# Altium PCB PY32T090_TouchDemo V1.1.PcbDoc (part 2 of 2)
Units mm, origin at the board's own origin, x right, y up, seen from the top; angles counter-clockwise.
Board outline 86.5 x 140.97 mm, 2 copper layers (Top Layer, Bottom Layer); 152 components, 143 nets, 461 pads, 174 vias.
Unrouted connection lines stored in the file: 2.
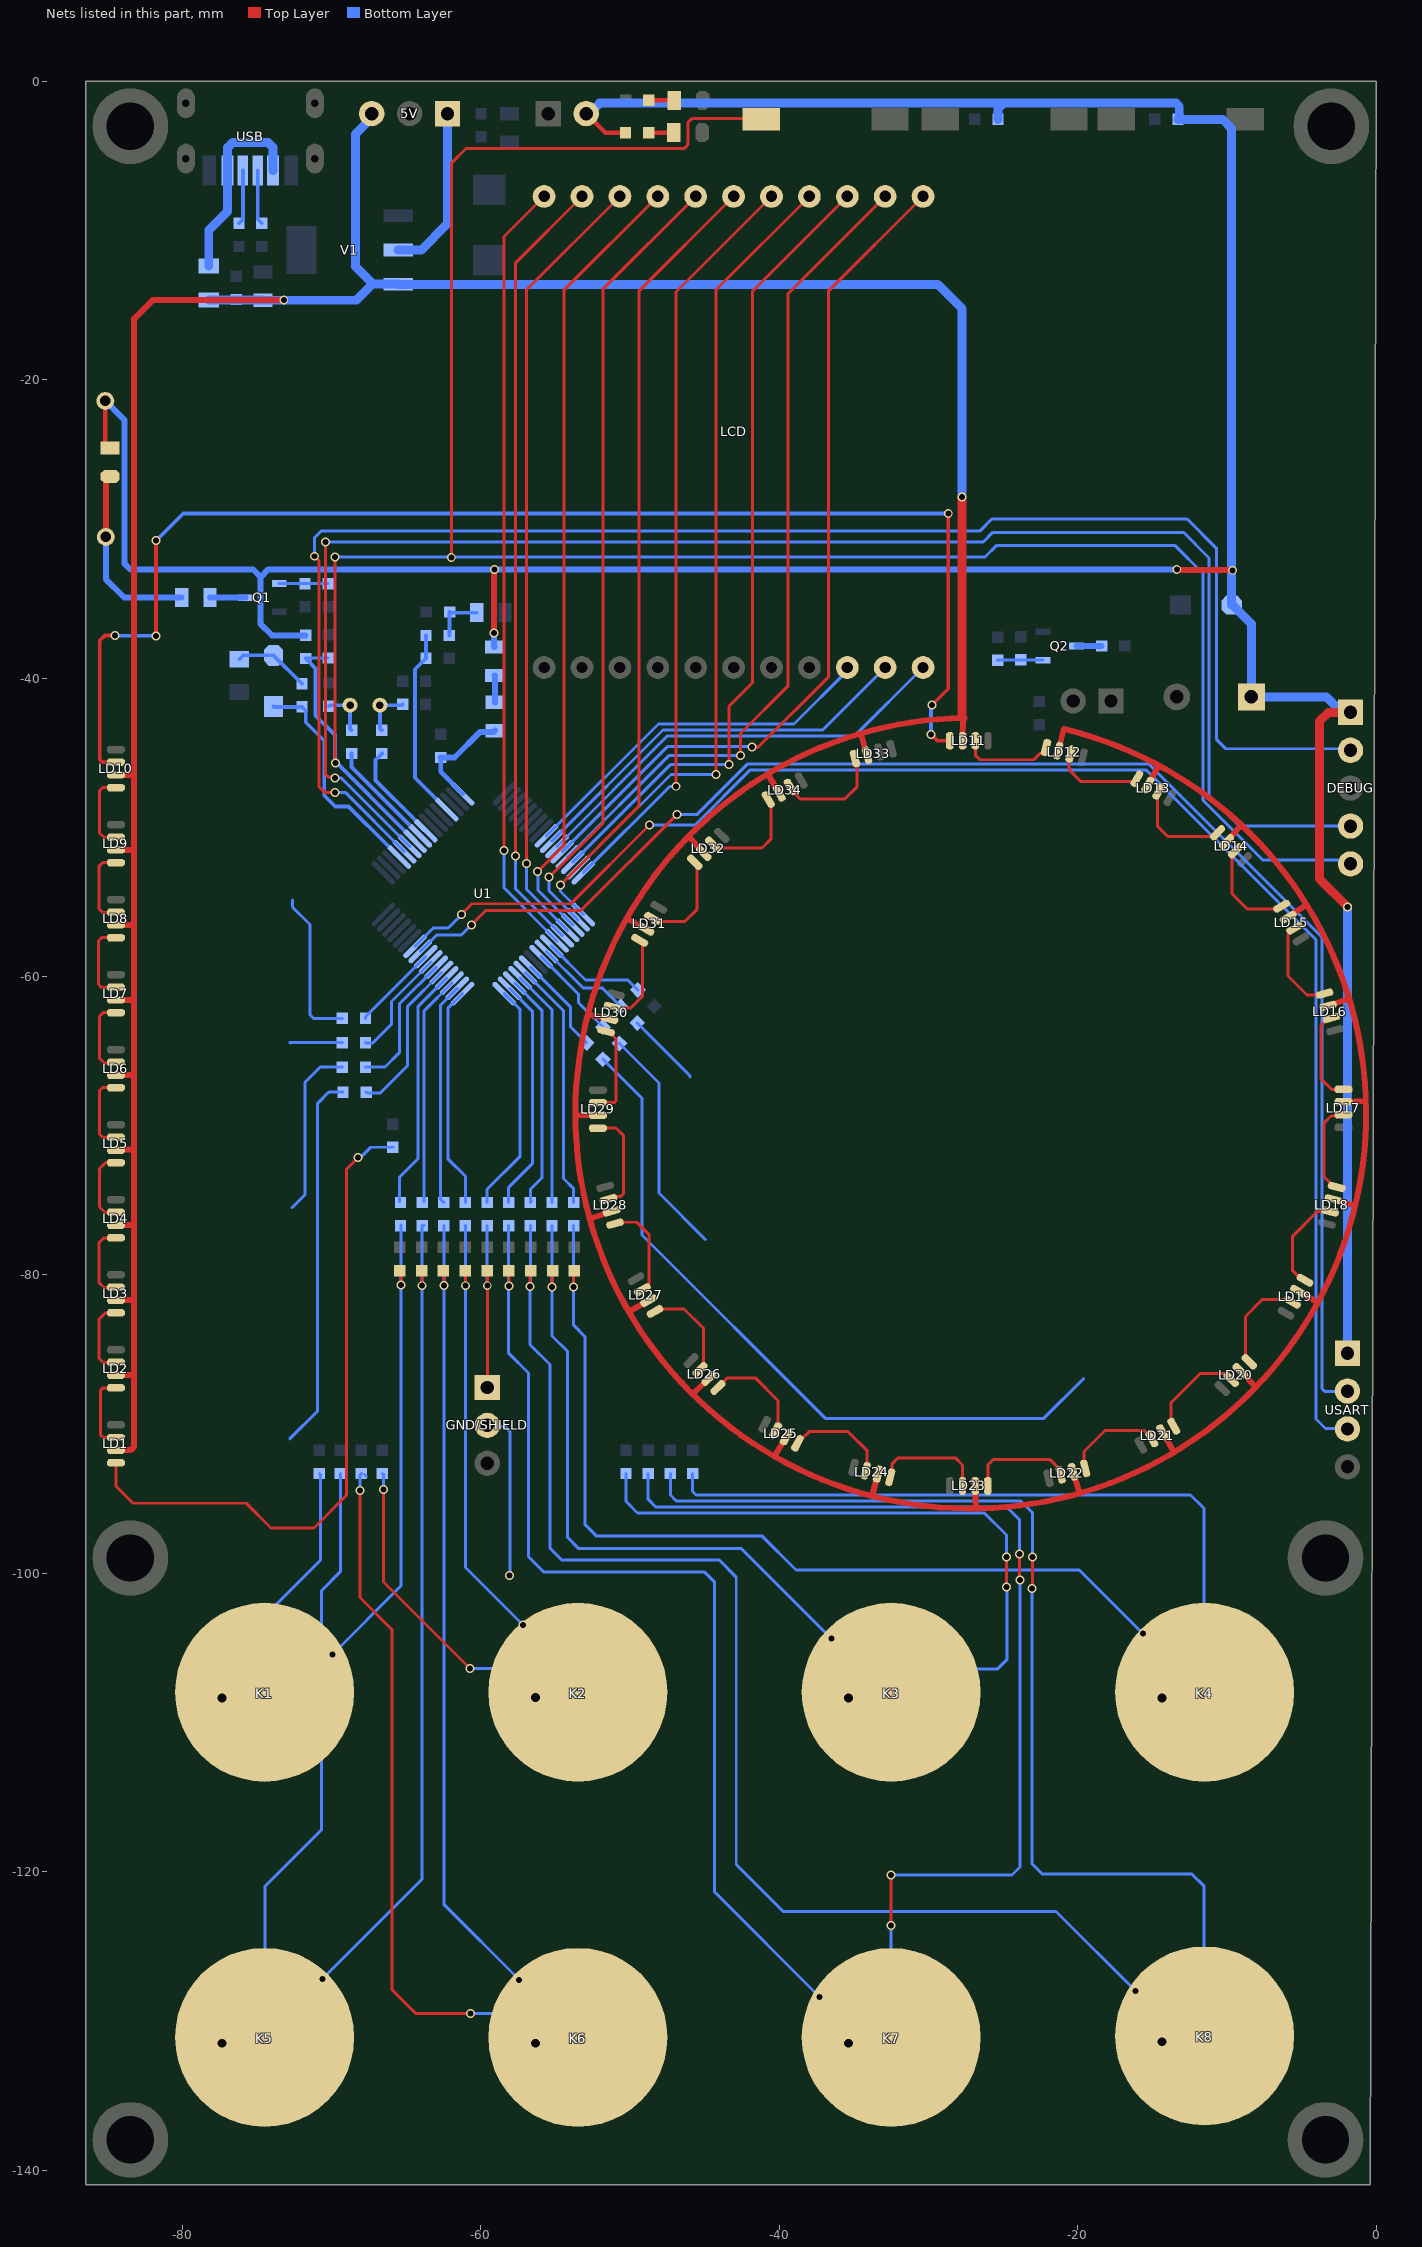
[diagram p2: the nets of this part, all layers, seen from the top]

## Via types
v1: diameter 0.6, hole 0.4, Top Layer to Bottom Layer, 174 vias

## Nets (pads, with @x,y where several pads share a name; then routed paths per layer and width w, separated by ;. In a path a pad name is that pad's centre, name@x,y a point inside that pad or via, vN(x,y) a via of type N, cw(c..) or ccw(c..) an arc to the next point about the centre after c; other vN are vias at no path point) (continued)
NetC4_2: GND/SHIELD.2 | length 11.4
  Bottom Layer w0.2: GND/SHIELD.2@-59.639,-90.145 -58.395,-90.145 -58.064,-90.475 -58.064,-100.101 v1@-58.039,-100.127
  other v1: -58.09,-100.152
NetC5_2: C5.2 Designator317.1 K1.Touch R9.2 | length 31.7
  Top Layer w0.2: C5.2@-65.443,-79.705 -65.367,-79.781 v1(-65.367,-80.67)
  Bottom Layer w0.2: v1(-69.952,-105.435) -65.367,-100.851 v1(-65.367,-80.67) R9.2@-65.367,-76.647
NetC8_2: R10.2 | length 5.1
  Bottom Layer w0.2: R10.2@-49.527,-63.11 -45.987,-66.65 -45.987,-66.726
NetC9_2: C9.2 Designator322.1 K5.Touch R12.2 | length 54.3
  Top Layer w0.2: C9.2@-63.98,-79.705 -63.945,-79.74 v1(-63.945,-80.721)
  Bottom Layer w0.2: v1(-70.612,-127.203) -70.612,-127.165 -63.942,-120.494 R12.2@-63.942,-76.698 ; R12.2@-63.803,-76.698 R12.2@-63.803,-76.647
NetC11_2: R13.2 | length 15.5
  Bottom Layer w0.2: R13.2@-50.721,-64.481 -48.07,-67.132 -48.07,-74.506 -44.958,-77.617
NetC12_2: C12.2 Designator321.1 K6.Touch R14.2 | length 53.7
  Top Layer w0.2: C12.2@-62.516,-79.705 -62.472,-79.75 v1(-62.472,-80.696)
  Bottom Layer w0.2: R14.2@-62.491,-76.698 -62.491,-122.18 -57.442,-127.229 v1(-57.442,-127.254)
NetC13_2: R15.2 | length 48.7
  Bottom Layer w0.2: R15.2@-51.822,-65.539 -49.213,-68.148 -49.213,-77.318 -36.894,-89.637 -22.302,-89.637 -19.603,-86.937
NetC14_2: C14.2 Designator316.1 K2.Touch R17.2 | length 29.4
  Top Layer w0.2: C14.2@-61.052,-79.705 -61.049,-79.708 v1(-61.049,-80.721)
  Bottom Layer w0.2: R17.2@-61.04,-76.698 -61.04,-99.603 v1(-57.188,-103.454)
NetC15_2: R18.2 | length 25.3
  Bottom Layer w0.2: -72.809,-90.983 -70.942,-89.116 -70.942,-68.491 -70.193,-67.742 R18.2@-69.243,-67.742
NetC16_2: C16.2 Designator320.1 K7.Touch R19.2 | length 67.7
  Top Layer w0.2: v1(-58.128,-80.747) -58.128,-79.708 C16.2@-58.125,-79.705
  Bottom Layer w0.2: R19.2@-58.138,-76.698 -58.138,-85.245 -56.82,-86.563 -56.82,-98.882 -55.804,-99.898 -45.034,-99.898 -44.336,-100.596 -44.336,-121.361 v1(-37.3,-128.397)
NetC17_2: C17.2 Designator319.1 K8.Touch R20.2 | length 86.1
  Top Layer w0.2: v1(-56.706,-80.772) -56.706,-79.75 C17.2@-56.661,-79.705
  Bottom Layer w0.2: v1(-56.706,-80.772) -56.706,-84.671 -55.372,-86.004 -55.372,-98.323 -54.585,-99.111 -44.031,-99.111 -42.888,-100.254 -42.888,-119.507 -39.739,-122.657 -21.451,-122.657 v1(-16.117,-127.991) ; v1@-56.687,-80.772 R20.2@-56.687,-76.698
NetC18_2: C18.2 R21.2 X1.1 | length 3.2
  Bottom Layer w0.254: C18.2@-70.193,-41.874 -70.127,-41.808 X1.1@-68.771,-41.808 -68.771,-43.394 R21.2@-68.669,-43.495
NetC19_2: R22.2 | length 11.7
  Bottom Layer w0.2: -72.657,-75.463 -72.632,-75.463 -71.78,-74.612 -71.78,-67.068 -70.777,-66.065 R22.2@-69.294,-66.065
NetC20_1: C20.1 R23.2 X1.2 | length 3.3
  Bottom Layer w0.254: R23.2@-66.637,-43.495 -66.771,-43.362 X1.2@-66.771,-41.808 -65.301,-41.808 C20.1@-65.24,-41.747
NetC21_2: C21.2 Designator315.1 K3.Touch R24.2 | length 42.9
  Top Layer w0.2: v1(-55.233,-80.797) -55.233,-79.74 C21.2@-55.198,-79.705
  Bottom Layer w0.2: R24.2@-55.236,-76.698 -55.233,-76.701 v1(-55.233,-80.797) -55.233,-84.086 -54.204,-85.115 -54.204,-97.587 -53.442,-98.349 -42.533,-98.349 v1(-36.513,-104.369)
NetC22_2: R25.2 | length 3.5
  Bottom Layer w0.2: -72.809,-64.44 -72.801,-64.431 R25.2@-69.294,-64.431
NetC23_2: C23.2 Designator318.1 K4.Touch R26.2 | length 61.9
  Top Layer w0.2: v1(-53.785,-80.797) -53.785,-79.756 C23.2@-53.734,-79.705
  Bottom Layer w0.2: R26.2@-53.785,-76.698 v1(-53.785,-80.797) -53.785,-83.375 -53.01,-84.15 -53.01,-96.749 -52.273,-97.485 -41.171,-97.485 -38.885,-99.771 -19.901,-99.771 v1(-15.634,-104.038)
NetC24_2: R27.2 | length 10.4
  Bottom Layer w0.2: -72.632,-54.864 -72.632,-55.347 -71.463,-56.515 -71.463,-62.56 -71.226,-62.797 R27.2@-69.294,-62.797
NetE3_1: E3.1 R28.2 VD2.2 | length 5.1
  Bottom Layer w0.254: E3.1@-76.188,-38.727 -75.929,-38.468 VD2.2@-73.902,-38.468 -73.899,-38.468 R28.2@-71.997,-40.371
NetJUMP_1: 5V.1 V1.2@-65.545,-11.303 | length 11.4
  Bottom Layer w0.6: V1.2@-65.545,-11.303 -64.008,-11.303 -62.243,-9.538 5V.1@-62.243,-2.159
NetLD1_1: LD1.1 R35.2 | length 44.7
  Top Layer w0.2: LD1.1@-84.468,-92.593 -84.468,-94.158 -83.325,-95.301 -75.73,-95.301 -74.079,-96.952 -71.196,-96.952 -68.999,-94.755 -68.999,-72.898 v1(-68.237,-72.136)
  Bottom Layer w0.2: v1(-68.237,-72.136) -68.085,-72.136 -67.389,-71.44 R35.2@-65.901,-71.44
NetLD1_3: LD1.3 LD2.1 | length 5.2
  Top Layer w0.2: LD1.3@-84.468,-90.893 -85.32,-90.893 -85.509,-90.703 -85.509,-87.757 -85.316,-87.564 LD2.1@-84.468,-87.564
NetLD2_3: LD2.3 LD3.1 | length 5.2
  Top Layer w0.2: LD2.3@-84.468,-85.864 -85.32,-85.864 -85.586,-85.598 -85.586,-82.956 -85.164,-82.535 LD3.1@-84.468,-82.535
NetLD3_3: LD3.3 LD4.1 | length 5.2
  Top Layer w0.2: LD3.3@-84.468,-80.835 -85.269,-80.835 -85.586,-80.518 -85.586,-77.826 -85.266,-77.506 LD4.1@-84.468,-77.506
NetLD4_3: LD4.3 LD5.1 | length 5.1
  Top Layer w0.2: LD4.3@-84.468,-75.806 -85.192,-75.806 -85.56,-75.438 -85.56,-72.873 -85.165,-72.477 LD5.1@-84.468,-72.477
NetLD5_3: LD5.3 LD6.1 | length 5.3
  Top Layer w0.2: LD5.3@-84.468,-70.777 -85.344,-70.777 -85.56,-70.561 -85.56,-67.64 -85.368,-67.448 LD6.1@-84.468,-67.448
NetLD6_3: LD6.3 LD7.1 | length 5.2
  Top Layer w0.2: LD6.3@-84.468,-65.748 -84.506,-65.786 -85.255,-65.786 -85.56,-65.481 -85.56,-62.662 -85.317,-62.419 LD7.1@-84.468,-62.419
NetLD7_3: LD7.3 LD8.1 | length 5.4
  Top Layer w0.2: LD7.3@-84.468,-60.719 -85.446,-60.719 -85.636,-60.528 -85.636,-57.607 -85.419,-57.39 LD8.1@-84.468,-57.39
NetLD8_3: LD8.3 LD9.1 | length 5.3
  Top Layer w0.2: LD8.3@-84.468,-55.69 -84.48,-55.702 -85.357,-55.702 -85.586,-55.474 -85.586,-52.603 -85.343,-52.361 LD9.1@-84.468,-52.361
NetLD9_3: LD9.3 LD10.1 | length 5.2
  Top Layer w0.2: LD9.3@-84.468,-50.661 -85.267,-50.661 -85.56,-50.368 -85.56,-47.549 -85.343,-47.332 LD10.1@-84.468,-47.332
NetLD10_3: LD10.3 LD11.1 | length 90.1
  Top Layer w0.254: v1(-84.519,-37.135) -85.205,-37.135 -85.547,-37.477 -85.547,-45.457 -85.373,-45.632 LD10.3@-84.468,-45.632 ; v1(-81.788,-30.785) -81.776,-30.797 v1(-81.776,-37.186) ; v1(-29.826,-43.764) -29.399,-44.192 LD11.1@-28.562,-44.192 ; v1(-29.782,-41.808) -28.677,-40.703 v1(-28.677,-28.956)
  Bottom Layer w0.254: v1(-84.519,-37.135) -84.493,-37.16 -81.801,-37.16 v1(-81.776,-37.186) ; v1(-81.788,-30.785) -79.959,-28.956 v1(-28.677,-28.956) ; v1(-29.826,-43.764) -29.826,-41.853 v1(-29.782,-41.808)
NetLD11_3: LD11.3 LD12.1 | length 6.3
  Top Layer w0.2: LD11.3@-26.862,-44.192 -26.862,-45.16 -26.556,-45.466 -22.946,-45.466 -22.54,-45.061 -22.387,-45.061 -22.123,-44.796 LD12.1@-22.123,-44.643
NetLD12_3: LD12.3 LD13.1 | length 6
  Top Layer w0.2: LD12.3@-20.481,-45.083 -20.571,-45.174 -20.571,-46.142 -19.797,-46.917 -16.205,-46.917 LD13.1@-16.03,-46.742
NetLD13_3: LD13.3 LD14.1 | length 6.8
  Top Layer w0.2: LD13.3@-14.557,-47.592 -14.665,-47.7 -14.665,-49.899 -13.959,-50.605 -10.87,-50.605 LD14.1@-10.623,-50.358
NetLD14_3: LD14.3 LD15.1 | length 6.8
  Top Layer w0.2: LD14.3@-9.418,-51.558 -9.665,-51.805 -9.665,-54.444 -8.649,-55.46 -6.505,-55.46 LD15.1@-6.327,-55.283
NetLD15_3: LD15.3 LD16.1 | length 6.4
  Top Layer w0.2: LD15.3@-5.465,-56.748 -5.476,-56.748 -5.914,-57.185 -5.914,-59.962 -4.635,-61.24 -3.56,-61.24 LD16.1@-3.464,-61.143
NetLD16_3: LD16.3 LD17.1 | length 6.3
  Top Layer w0.2: LD16.3@-2.995,-62.777 -3.165,-62.777 -3.706,-63.318 -3.706,-66.843 -2.995,-67.554 LD17.1@-2.197,-67.554
NetLD17_3: LD17.3 LD18.1 | length 6.3
  Top Layer w0.2: LD18.1@-2.645,-74.105 -2.798,-74.105 -3.505,-73.398 -3.505,-69.827 -3.016,-69.338 -2.281,-69.338 LD17.3@-2.197,-69.254
NetLD18_3: LD18.3 LD19.1 | length 6.6
  Top Layer w0.2: LD19.1@-4.768,-80.351 -4.955,-80.351 -5.588,-79.718 -5.588,-77.404 -3.92,-75.736 -3.096,-75.736 LD18.3@-3.085,-75.747
NetLD19_3: LD19.3 LD20.1 | length 6.8
  Top Layer w0.2: LD20.1@-8.51,-85.81 -8.758,-85.563 -8.758,-82.786 -7.608,-81.636 -5.806,-81.636 LD19.3@-5.618,-81.823
NetLD20_3: LD20.3 LD21.1 | length 6.7
  Top Layer w0.2: LD21.1@-13.558,-90.139 -13.733,-89.964 -13.733,-88.548 -11.773,-86.589 -10.136,-86.589 LD20.3@-9.712,-87.012
NetLD21_3: LD21.3 LD22.1 | length 6.6
  Top Layer w0.2: LD22.1@-19.494,-92.964 -19.584,-92.873 -19.584,-91.834 -18.174,-90.424 -15.532,-90.424 -15.03,-90.926 LD21.3@-15.03,-90.989
NetLD22_3: LD22.3 LD23.1 | length 7.1
  Top Layer w0.2: LD23.1@-26.023,-94.137 -26.023,-92.736 -25.642,-92.354 -21.882,-92.354 -21.136,-93.101 LD22.3@-21.136,-93.404
NetLD23_3: LD23.3 LD24.1 | length 7.5
  Top Layer w0.2: LD24.1@-32.564,-93.558 -32.436,-93.43 -32.436,-92.646 -32.042,-92.253 -28.207,-92.253 -27.724,-92.735 -27.724,-94.138 LD23.3@-27.75,-94.164
NetLD24_3: LD24.3 LD25.1 | length 6.9
  Top Layer w0.2: LD25.1@-38.784,-91.282 -38.784,-91.266 -38.43,-90.912 -38.414,-90.912 -38.003,-90.5 -35.395,-90.5 -34.115,-91.78 -34.115,-93.028 LD24.3@-34.206,-93.118
NetLD25_3: LD25.3 LD26.1 | length 7
  Top Layer w0.2: LD26.1@-44.117,-87.54 -43.47,-86.893 -41.618,-86.893 -40.081,-88.43 -40.081,-90.257 LD25.3@-40.256,-90.432
NetLD26_3: LD26.3 LD27.1 | length 6.7
  Top Layer w0.2: LD27.1@-48.331,-82.448 -48.156,-82.273 -46.391,-82.273 -45.071,-83.593 -45.071,-86.091 LD26.3@-45.319,-86.338
NetLD27_3: LD27.3 LD28.1 | length 6.6
  Top Layer w0.2: LD28.1@-51.016,-76.557 -50.926,-76.466 -49.556,-76.466 -48.723,-77.299 -48.723,-80.534 -49.165,-80.976 LD27.3@-49.181,-80.976
NetLD28_3: LD28.3 LD29.1 | length 7
  Top Layer w0.2: LD29.1@-52.164,-70.155 -50.94,-70.155 -50.457,-70.637 -50.457,-74.574 -50.628,-74.745 -51.286,-74.745 LD28.3@-51.456,-74.914
NetLD29_3: LD29.3 LD30.1 | length 6.3
  Top Layer w0.2: LD29.3@-52.164,-68.455 -51.069,-68.455 -50.94,-68.326 -50.94,-64.182 -51.457,-63.664 LD30.1@-51.61,-63.664
NetLD30_3: LD30.3 LD31.1 | length 6.2
  Top Layer w0.2: LD30.3@-51.17,-62.022 -51.08,-62.113 -49.959,-62.113 -49.185,-61.338 -49.185,-57.746 LD31.1@-49.36,-57.571
NetLD31_3: LD31.3 LD32.1 | length 6.6
  Top Layer w0.2: LD31.3@-48.51,-56.099 -48.296,-56.312 -46.343,-56.312 -45.51,-55.479 -45.51,-52.499 LD32.1@-45.669,-52.34
NetLD32_3: LD32.3 LD34.1 | length 7
  Top Layer w0.2: LD32.3@-44.467,-51.138 -44.219,-51.386 -41.163,-51.386 -40.573,-50.796 -40.573,-48.313 LD34.1@-40.748,-48.138
NetLD33_3: LD33.1 LD34.3 | length 7.2
  Top Layer w0.2: LD34.3@-39.276,-47.288 -39.276,-47.417 -38.61,-48.082 -35.598,-48.082 -34.786,-47.269 -34.786,-45.543 LD33.1@-34.939,-45.39
NetLED1_2: LED1.2 pad.3 R2.2 | length 12.6
  Top Layer w0.4: pad.3@-85.141,-30.531 -85.141,-26.769 LED1.2@-84.849,-26.477
  Bottom Layer w0.4: pad.3@-85.141,-30.531 -85.141,-33.363 -83.909,-34.595 R2.2@-80.059,-34.595
NetLED2_1: LED2.1 R3.1 | length 1.7
  Top Layer w0.3: R3.1@-48.741,-1.27 LED2.1@-47.039,-1.27
NetLED3_1: LED3.1 R44.1 | length 1.7
  Top Layer w0.3: R44.1@-48.756,-3.429 LED3.1@-47.1,-3.429
NetLED4_1: K1.1 R30.2 | length 14.7
  Bottom Layer w0.2: K1.1@-74.525,-106.372 -74.377,-106.372 -73.927,-105.922 -73.927,-102.286 -70.762,-99.12 -70.762,-93.376 R30.2@-70.828,-93.309
NetLED5_1: K2.1 R31.2 | length 22.9
  Top Layer w0.2: v1(-66.536,-94.386) -66.536,-100.578 v1(-60.741,-106.372)
  Bottom Layer w0.2: R31.2@-66.612,-93.309 -66.536,-93.385 v1(-66.536,-94.386) ; R31.2@-66.536,-93.36 R31.2@-66.485,-93.411 ; v1@-60.846,-106.477 v1(-60.741,-106.372) K2.1@-53.525,-106.372
NetLED6_1: K3.1 R32.2 | length 44.7
  Top Layer w0.2: v1(-24.778,-100.914) v1(-24.778,-98.908)
  Bottom Layer w0.2: R32.2@-50.28,-93.309 -50.28,-95.174 -49.505,-95.949 -26.264,-95.949 -24.778,-97.434 v1(-24.778,-98.908) ; K3.1@-32.525,-106.372 -32.496,-106.401 -25.362,-106.401 -24.753,-105.791 -24.753,-100.94 v1(-24.778,-100.914) v1@-24.803,-100.889
NetLED7_1: K4.1 R33.2 | length 46.7
  Bottom Layer w0.2: R33.2@-45.809,-93.309 -45.809,-94.513 -45.581,-94.742 -12.434,-94.742 -11.525,-95.651 K4.1@-11.525,-106.372
NetLED8_1: K5.1 R38.2 | length 38.4
  Bottom Layer w0.2: K5.1@-74.525,-129.504 -74.463,-129.565 -74.463,-120.957 -70.676,-117.17 -70.676,-101.143 -69.423,-99.89 R38.2@-69.423,-93.309
NetLED9_1: K6.1 R39.2 | length 48.8
  Top Layer w0.2: v1(-68.11,-94.437) -68.11,-101.625 -65.973,-103.762 -65.973,-127.892 -64.362,-129.504 v1(-60.708,-129.504)
  Bottom Layer w0.2: v1(-68.11,-94.437) -68.11,-93.402 R39.2@-68.017,-93.309 ; R39.2@-67.806,-93.385 R39.2@-67.679,-93.512 ; v1@-60.719,-129.515 v1(-60.708,-129.504) K6.1@-53.525,-129.504
NetLED10_1: K7.1 R40.2 | length 69.1
  Top Layer w0.2: v1(-32.525,-123.597) v1(-32.525,-120.218) ; v1(-23.914,-98.704) -23.914,-100.406 v1(-23.864,-100.457)
  Bottom Layer w0.2: R40.2@-48.789,-93.309 -48.789,-95.038 -48.279,-95.549 -24.759,-95.549 -23.914,-96.393 v1(-23.914,-98.704) ; K7.1@-32.838,-129.54 -32.875,-129.504 K7.1@-32.525,-129.504 v1(-32.525,-123.597) v1@-32.55,-123.571 ; v1(-32.525,-120.218) -24.397,-120.218 -23.864,-119.685 v1(-23.864,-100.457)
NetLED11_1: K8.1 R41.2 | length 70.3
  Top Layer w0.2: v1(-23.063,-101.028) -23.025,-100.99 v1(-23.025,-98.908)
  Bottom Layer w0.2: R41.2@-47.299,-93.309 -47.299,-94.75 -46.901,-95.149 -23.812,-95.149 -23.025,-95.936 v1(-23.025,-98.908) ; v1(-23.063,-101.028) -23.063,-119.469 -22.365,-120.167 -12.332,-120.167 -11.525,-120.975 K8.1@-11.525,-129.402
NetQ1_1: Q1.1 R5.1 R6.2 | length 3.3
  Bottom Layer w0.2: Q1.1@-73.521,-33.655 -70.254,-33.655 R5.1@-70.244,-33.665
NetQ1_3: Q1.3 R2.1 | length 2.4
  Bottom Layer w0.4: R2.1@-78.159,-34.595 -78.148,-34.605 Q1.3@-75.789,-34.605
NetQ2_1: Q2.1 R36.1 R37.2 | length 3
  Bottom Layer w0.2: R36.1@-25.362,-38.801 -25.357,-38.796 Q2.1@-22.34,-38.796
NetQ2_3: Q2.3 R34.1 | length 1.7
  Bottom Layer w0.4: Q2.3@-20.072,-37.846 R34.1@-18.392,-37.846
NetR1_2: R1.2 USB.A5 | length 3.6
  Bottom Layer w0.254: R1.2@-76.213,-9.51 -75.955,-9.252 USB.A5@-75.955,-5.969
NetR4_2: R4.2 USB.B5 | length 3.7
  Bottom Layer w0.254: USB.B5@-74.955,-5.969 -74.955,-9.244 R4.2@-74.689,-9.51
NetR42_1: R42.1 R43.1 RT1.2 | length 3.4
  Bottom Layer w0.254: R42.1@-62.126,-37.135 -62.101,-37.109 R43.1@-62.101,-35.56 -62.05,-35.611 RT1.2@-60.287,-35.611
NRST: C10.2 DEBUG.5 R11.1 RST.2 U1.7 | length 164.4
  Top Layer w0.2: v1(-69.761,-45.669) -69.774,-45.657 -69.774,-31.915 v1@-69.761,-31.902 ; v1(-61.989,-31.902) -61.989,-5.492 -60.997,-4.501 -46.373,-4.501 -46.114,-4.242 -46.114,-2.743 -45.865,-2.494 -41.258,-2.494 RST.2@-41.212,-2.54
  Top Layer w0.254: v1(-69.787,-31.877) v1@-69.761,-31.902
  Bottom Layer w0.2: R11.1@-71.743,-38.684 -71.707,-38.648 C10.2@-70.244,-38.648 ; v1(-69.787,-31.877) -26.213,-31.877 -25.425,-31.09 -13.5,-31.09 -11.603,-32.987 -11.603,-48.176 -7.582,-52.197 -2.553,-52.197 DEBUG.5@-2.299,-52.451
  Bottom Layer w0.254: R11.1@-71.743,-38.684 -71.082,-39.345 -71.082,-42.52 -69.787,-43.815 -69.787,-45.551 -65.183,-50.155
NTC: C25.2 R42.2 U1.13 | length 11.8
  Bottom Layer w0.254: R42.2@-63.68,-37.135 C25.2@-63.68,-38.659 -64.427,-39.406 -64.427,-46.668 -63.062,-48.034
OSC32I: R21.1 U1.8 | length 6.3
  Bottom Layer w0.254: R21.1@-68.669,-45.049 -68.669,-45.962 -64.829,-49.801
OSC32O: R23.1 U1.9 | length 5.7
  Bottom Layer w0.254: R23.1@-66.637,-45.049 -67.069,-45.481 -67.069,-46.855 -64.476,-49.448
POWER: R28.1 U1.4 VD2.1 | length 14.1
  Bottom Layer w0.254: VD2.1@-73.902,-41.897 -73.874,-41.925 R28.1@-71.997,-41.925 -71.743,-42.179 -71.743,-42.951 -70.498,-44.196 -70.498,-47.854 -69.761,-48.59 -68.869,-48.59 -66.244,-51.216
SEG0: LCD.9 U1.25 | length 25
  Bottom Layer w0.2: U1.25@-55.61,-50.569 -48.106,-43.066 -39.015,-43.066 -35.446,-39.497 LCD.9@-35.446,-39.284
SEG1: LCD.10 U1.26 | length 27.2
  Bottom Layer w0.2: U1.26@-55.256,-50.922 -47.799,-43.466 -37.087,-43.466 LCD.10@-32.906,-39.284
SEG2: LCD.11 U1.27 | length 29.5
  Bottom Layer w0.2: U1.27@-54.902,-51.276 -47.492,-43.866 -34.947,-43.866 LCD.11@-30.366,-39.284
SEG3: LCD.12 U1.28 | length 57.5
  Top Layer w0.2: v1(-41.821,-44.602) -41.39,-44.602 -36.716,-39.929 -36.716,-14.056 LCD.12@-30.366,-7.706
  Bottom Layer w0.2: U1.28@-54.549,-51.629 -47.511,-44.591 -41.832,-44.591 v1(-41.821,-44.602)
SEG4: LCD.13 U1.29 | length 55.9
  Top Layer w0.2: v1(-42.604,-45.191) -42.604,-43.709 -39.408,-40.513 -39.408,-14.208 LCD.13@-32.906,-7.706
  Bottom Layer w0.2: U1.29@-54.195,-51.983 -47.383,-45.171 -42.625,-45.171 v1(-42.604,-45.191)
SEG5: LCD.14 U1.30 | length 54.5
  Top Layer w0.2: v1(-43.371,-45.771) -43.371,-41.885 -41.796,-40.31 -41.796,-14.056 LCD.14@-35.446,-7.706
  Bottom Layer w0.2: U1.30@-53.842,-52.336 -47.276,-45.771 v1(-43.371,-45.771)
SEG6: LCD.15 U1.31 | length 53.2
  Top Layer w0.2: v1(-44.26,-46.457) -44.26,-13.979 LCD.15@-37.986,-7.706
  Bottom Layer w0.2: U1.31@-53.488,-52.69 -47.255,-46.457 v1(-44.26,-46.457)
SEG7: LCD.16 U1.32 | length 50.8
  Top Layer w0.2: v1(-46.927,-47.244) -46.927,-14.106 LCD.16@-40.526,-7.706
  Bottom Layer w0.2: U1.32@-53.135,-53.044 -47.335,-47.244 v1(-46.927,-47.244)
SEG8: LCD.17 U1.33 | length 53.6
  Top Layer w0.2: v1(-54.674,-53.848) -49.416,-48.59 -49.416,-14.056 LCD.17@-43.066,-7.706
  Bottom Layer w0.2: v1(-54.674,-53.848) -54.674,-54.3 U1.33@-53.135,-55.839
SEG9: LCD.18 U1.34 | length 53.4
  Top Layer w0.2: v1(-55.436,-53.34) -51.804,-49.708 -51.804,-13.903 LCD.18@-45.606,-7.706
  Bottom Layer w0.2: v1(-55.436,-53.34) -55.436,-54.245 U1.34@-53.488,-56.193
SEG10: LCD.19 U1.35 | length 53.2
  Top Layer w0.2: v1(-56.198,-52.959) -54.445,-51.206 -54.445,-14.005 LCD.19@-48.146,-7.706
  Bottom Layer w0.2: v1(-56.198,-52.959) -56.172,-52.984 -56.172,-54.216 U1.35@-53.842,-56.547
SEG11: LCD.20 U1.36 | length 52.9
  Top Layer w0.2: v1(-56.934,-52.426) -56.934,-13.954 LCD.20@-50.686,-7.706
  Bottom Layer w0.2: v1(-56.934,-52.426) -56.934,-54.161 U1.36@-54.195,-56.9
SEG12: LCD.21 U1.37 | length 52.7
  Top Layer w0.2: v1(-57.671,-51.918) -57.671,-12.151 LCD.21@-53.226,-7.706
  Bottom Layer w0.2: v1(-57.671,-51.918) -57.671,-54.131 U1.37@-54.549,-57.254
SEG13: LCD.22 U1.38 | length 52.5
  Top Layer w0.2: v1(-58.458,-51.562) -58.458,-10.398 LCD.22@-55.766,-7.706
  Bottom Layer w0.2: v1(-58.458,-51.562) -58.458,-54.051 U1.38@-54.902,-57.607
Shield: R8.1 U1.48 | length 15.4
  Bottom Layer w0.2: R8.1@-59.589,-75.144 -59.589,-74.257 -57.366,-72.034 -57.366,-62.214 U1.48@-58.438,-61.143
shield_pad: C4.2 GND/SHIELD.1 R8.2 | length 12
  Top Layer w0.2: GND/SHIELD.1@-59.639,-87.605 GND/SHIELD.1@-59.576,-87.541 v1(-59.576,-80.721) -59.576,-79.718 C4.2@-59.589,-79.705
  Bottom Layer w0.2: R8.2@-59.589,-76.698 -59.589,-80.708 v1(-59.576,-80.721)
Slider0: R7.1 U1.39 | length 7
  Bottom Layer w0.2: U1.39@-55.256,-57.961 -52.993,-60.223 -50.153,-60.223 R7.1@-49.483,-60.893
Slider1: R10.1 U1.40 | length 6.5
  Bottom Layer w0.2: U1.40@-55.61,-58.314 -53.167,-60.757 -51.88,-60.757 R10.1@-50.626,-62.011
Slider2: R13.1 U1.41 | length 6.4
  Bottom Layer w0.2: U1.41@-55.963,-58.668 -53.455,-61.176 -53.455,-61.747 R13.1@-51.82,-63.382
Slider3: R15.1 U1.43 | length 6.6
  Bottom Layer w0.2: U1.43@-56.67,-59.375 -53.988,-62.057 -53.988,-63.373 R15.1@-52.921,-64.44
SWC: DEBUG.4 U1.6 | length 109.1
  Top Layer w0.2: v1@-70.396,-30.861 v1(-70.409,-30.874) -70.422,-30.886 -70.422,-46.431 -70.244,-46.609 -69.863,-46.609 v1(-69.787,-46.685)
  Bottom Layer w0.2: v1(-70.409,-30.874) -26.34,-30.874 -25.692,-30.226 -12.916,-30.226 -11.203,-31.939 -11.203,-47.89 -9.182,-49.911 DEBUG.4@-2.299,-49.911 ; v1(-69.787,-46.685) -69.36,-46.685 U1.6@-64.769,-51.276
SWD: DEBUG.2 U1.5 | length 107.6
  Top Layer w0.2: v1(-71.158,-31.826) -70.854,-32.131 -70.854,-47.269 -70.473,-47.65 v1(-69.787,-47.65)
  Bottom Layer w0.2: v1(-71.158,-31.826) -71.158,-30.582 -70.727,-30.15 -26.568,-30.15 -25.756,-29.337 -12.662,-29.337 -10.713,-31.286 -10.713,-44.088 -10.071,-44.729 -2.401,-44.729 DEBUG.2@-2.299,-44.831 ; v1(-69.787,-47.65) -69.102,-47.65 U1.5@-65.123,-51.629
TK0: R9.1 U1.52 | length 16.3
  Bottom Layer w0.2: R9.1@-65.443,-75.093 -65.443,-73.431 -64.203,-72.191 -64.203,-61.991 U1.52@-62.294,-60.082
TK1: R12.1 U1.51 | length 15.4
  Bottom Layer w0.2: R12.1@-63.803,-75.093 -63.803,-62.298 U1.51@-61.941,-60.436
TK2: R14.1 U1.50 | length 14.9
  Bottom Layer w0.2: R14.1@-62.544,-75.093 R14.1@-62.544,-75.09 ; R14.1@-62.491,-75.144 R14.1@-62.544,-75.09 ; U1.50@-61.587,-60.789 -62.7,-61.902 -62.7,-74.934 R14.1@-62.544,-75.09
TK3: R17.1 U1.49 | length 14.9
  Bottom Layer w0.2: U1.49@-61.234,-61.143 -62.218,-62.127 -62.218,-72.212 -61.04,-73.39 R17.1@-61.04,-75.144
TK4: R19.1 U1.47 | length 15.6
  Bottom Layer w0.2: R19.1@-58.138,-75.144 -58.138,-74.127 -56.553,-72.542 -56.553,-62.32 U1.47@-58.084,-60.789
TK5: R20.1 U1.46 | length 15.9
  Bottom Layer w0.2: U1.46@-57.731,-60.436 -55.918,-62.248 -55.918,-73.508 -56.687,-74.276 R20.1@-56.687,-75.144 ; R20.1@-56.659,-75.093 R20.1@-56.604,-75.038
TK6: R24.1 U1.45 | length 15.9
  Bottom Layer w0.2: U1.45@-57.377,-60.082 -55.236,-62.224 R24.1@-55.236,-75.144
TK7: R26.1 U1.44 | length 16.8
  Bottom Layer w0.2: U1.44@-57.024,-59.729 -54.471,-62.282 -54.471,-73.533 -53.785,-74.219 R26.1@-53.785,-75.144
USART1_RX: U1.57 USART.2 | length 102.5
  Top Layer w0.2: v1(-60.643,-56.54) -59.678,-55.575 -53.302,-55.575 v1(-46.851,-49.124)
  Bottom Layer w0.2: U1.57@-64.062,-58.314 -62.949,-57.201 -61.303,-57.201 v1(-60.643,-56.54) ; v1(-46.851,-49.124) -45.494,-49.124 -42.11,-45.74 -15.259,-45.74 -3.626,-57.372 -3.626,-87.624 -3.449,-87.801 -1.963,-87.801 USART.2@-1.931,-87.769
USART1_TX: U1.58 USART.3 | length 104.5
  Top Layer w0.2: v1(-61.303,-55.829) -60.592,-55.118 -53.988,-55.118 v1(-48.705,-49.835)
  Bottom Layer w0.2: U1.58@-64.416,-57.961 -63.199,-56.744 -62.192,-56.744 -61.303,-55.855 v1(-61.303,-55.829) ; v1(-48.705,-49.835) -45.64,-49.835 -41.944,-46.14 -15.424,-46.14 -4.026,-57.538 -4.026,-89.662 -3.391,-90.297 -1.943,-90.297 USART.3@-1.918,-90.322
V5V: 5V.3 C1.2 E1.1 F1.2 LD1.2 LD2.2 LD3.2 LD4.2 LD5.2 LD6.2 LD7.2 LD8.2 LD9.2 LD10.2 LD11.2 LD12.2 LD13.2 LD14.2 LD15.2 LD16.2 LD17.2 LD18.2 LD19.2 LD20.2 LD21.2 LD22.2 LD23.2 LD24.2 LD25.2 LD26.2 LD27.2 LD28.2 LD29.2 LD30.2 LD31.2 LD32.2 LD33.2 LD34.2 V1.3 | length 383.9
  Top Layer w0.4: LD1.2@-84.468,-91.743 -83.483,-91.743 -83.249,-91.509 -83.249,-86.585 ; LD2.2@-84.468,-86.714 -83.378,-86.714 -83.249,-86.585 ; LD3.2@-84.468,-81.685 -83.273,-81.685 -83.249,-81.661 ; LD4.2@-84.468,-76.656 -83.298,-76.656 -83.249,-76.606 ; LD5.2@-84.468,-71.627 -84.426,-71.585 -83.282,-71.585 -83.249,-71.552 ; LD6.2@-84.468,-66.598 -83.324,-66.598 -83.249,-66.523 ; LD7.2@-84.468,-61.569 -83.275,-61.569 -83.249,-61.595 ; LD8.2@-84.468,-56.54 -83.325,-56.54 -83.249,-56.464 ; LD9.2@-84.468,-51.511 -83.274,-51.511 -83.249,-51.537 ; LD10.2@-84.468,-46.482 -83.274,-46.482 -83.249,-46.457 ; v1(-73.216,-14.656) -82.004,-14.656 -83.249,-15.9 -83.249,-46.457 ; -53.671,-69.292 LD29.2@-52.164,-69.305 ; -52.83,-62.531 LD30.2@-51.39,-62.843 ; -52.515,-76.175 LD28.2@-51.236,-75.736 ; -50.087,-82.467 LD27.2@-48.756,-81.712 ; -50,-56.21 LD31.2@-48.935,-56.835 ; -45.911,-50.775 LD32.2@-45.068,-51.739 ; -45.657,-87.833 LD26.2@-44.718,-86.939 ; -40.778,-46.417 LD34.2@-40.012,-47.713 ; -40.196,-91.923 LD25.2@-39.52,-90.857 ; -34.481,-43.917 LD33.2@-34.118,-45.17 ; -33.784,-94.819 LD24.2@-33.385,-93.338 ; LD11.2@-27.712,-44.192 -27.702,-42.663 ; -27.634,-42.662 ccw(c-27.171,-69.158) -20.76,-43.445 ; LD23.2@-26.873,-94.137 -26.809,-95.655 ; LD12.2@-21.302,-44.863 -20.93,-43.403 ; LD22.2@-20.315,-93.184 -19.927,-94.437 ; LD13.2@-15.293,-47.167 -14.564,-45.849 ; LD21.2@-14.294,-90.564 -13.543,-91.885 ; LD14.2@-10.021,-50.958 -9.035,-49.836 ; LD20.2@-9.111,-86.411 -8.055,-87.51 ; LD15.2@-5.896,-56.015 -4.839,-55.296 ; LD19.2@-5.193,-81.087 -3.905,-81.843 ; LD16.2@-3.229,-61.96 -2.02,-61.544 ; LD18.2@-2.865,-74.926 -1.408,-75.361 ; LD17.2@-2.197,-68.404 -0.74,-68.341 ; -83.249,-86.585 -83.249,-81.661 ; -83.249,-81.661 -83.249,-76.606 ; -83.249,-76.606 -83.249,-71.552 ; -83.249,-71.552 -83.249,-66.523 ; -83.249,-66.523 -83.249,-61.595 ; -83.249,-61.595 -83.249,-56.464 ; -83.249,-56.464 -83.249,-51.537 ; -83.249,-51.537 -83.249,-46.457
  Top Layer w0.6: v1(-27.75,-27.864) -27.75,-42.615 -27.702,-42.663
  Bottom Layer w0.6: F1.2@-78.245,-14.656 -78.24,-14.661 -74.618,-14.661 E1.1@-74.613,-14.666 -68.349,-14.666 -67.247,-13.564 ; 5V.3@-67.323,-2.159 -67.323,-2.449 -68.415,-3.542 -68.415,-12.395 -67.247,-13.564 ; v1(-27.75,-27.864) -27.75,-15.24 -29.387,-13.603 V1.3@-65.545,-13.603 -65.584,-13.564 -67.247,-13.564
VBUS: F1.1 USB.A9 USB.B9 | length 13.3
  Bottom Layer w0.6: F1.1@-78.245,-12.37 -78.245,-9.97 -76.975,-8.7 USB.B9@-76.975,-5.969 -76.975,-4.441 -76.624,-4.089 -74.286,-4.089 -73.935,-4.441 USB.A9@-73.935,-5.969
VCC: BEEP1.1 C6.2 DEBUG.1 L1.1 L1.2 LED1.1 pad.2 R11.2 R16.2 R29.2 R44.2 R45.1 R45.2 U1.16 USART.1 VCC_JUMP.2 VD1.2 | length 253
  Top Layer w0.3: pad.2@-85.177,-21.415 -85.177,-24.282 -84.882,-24.577 LED1.1@-84.849,-24.577 ; VCC_JUMP.2@-52.947,-2.159 -51.677,-3.429 R44.2@-50.31,-3.429 ; v1(-13.361,-32.703) v1@-13.329,-32.734 ; v1@-9.671,-32.734 v1(-9.64,-32.766)
  Top Layer w0.4: v1@-59.106,-36.982 v1(-59.131,-36.957) -59.118,-36.944 -59.118,-32.728 v1(-59.106,-32.715) ; v1@-13.329,-32.734 v1@-9.671,-32.734
  Top Layer w0.6: v1(-1.918,-55.321) -3.798,-53.442 -3.798,-42.901 -3.188,-42.291 DEBUG.1@-1.715,-42.291
  Bottom Layer w0.3: C6.2@-62.7,-45.316 -62.7,-46.274 U1.16@-61.234,-47.74
  Bottom Layer w0.4: pad.2@-85.177,-21.415 -83.884,-22.708 -83.884,-32.334 -83.503,-32.715 -75.273,-32.715 -74.765,-33.223 ; R11.2@-71.743,-37.13 -74.008,-37.13 -74.765,-36.373 -74.765,-33.223 ; C6.2@-62.7,-45.316 -61.775,-45.316 -60.056,-43.596 -59.131,-43.596 R45.2@-59.055,-43.52 ; v1(-59.131,-36.957) -59.131,-37.861 L1.2@-59.08,-37.912 ; L1.1@-59.08,-39.812 -59.055,-39.838 R45.1@-59.055,-41.62 ; -24.676,-32.703 v1(-13.361,-32.703) ; -22.372,-32.715 v1(-59.106,-32.715) -59.118,-32.703 -74.244,-32.703 -74.765,-33.223
  Bottom Layer w0.6: VCC_JUMP.2@-52.947,-2.159 -52.756,-2.159 -52.045,-1.448 -24.953,-1.448 ; R16.2@-25.347,-2.54 -25.347,-1.842 -24.953,-1.448 ; DEBUG.1@-2.197,-42.393 -3.34,-41.25 BEEP1.1@-8.359,-41.25 -8.359,-36.358 -9.614,-35.103 VD1.2@-9.678,-35.103 -9.678,-3.158 -10.296,-2.54 R29.2@-13.282,-2.54 -13.196,-2.453 -13.196,-1.676 -13.424,-1.448 -24.953,-1.448 ; USART.1@-1.918,-85.242 v1(-1.918,-55.321)
Wheel0: R18.1 U1.53 | length 10.8
  Bottom Layer w0.2: R18.1@-67.689,-67.742 -67.613,-67.818 -66.764,-67.818 -64.91,-65.964 -64.91,-61.99 U1.53@-62.648,-59.729
Wheel1: R22.1 U1.54 | length 9.4
  Bottom Layer w0.2: R22.1@-67.74,-66.065 -66.434,-66.065 -65.469,-65.1 -65.469,-61.842 U1.54@-63.002,-59.375
Wheel2: R25.1 U1.55 | length 7.5
  Bottom Layer w0.2: R25.1@-67.74,-64.431 -67.706,-64.465 -67.272,-64.465 -66.002,-63.195 -66.002,-61.668 U1.55@-63.355,-59.021
Wheel3: R27.1 U1.56 | length 5.8
  Bottom Layer w0.2: R27.1@-67.74,-62.797 -67.74,-62.699 U1.56@-63.709,-58.668
pads on no net: Designator207.1 Designator208.1 Designator209.1 Designator210.1 Designator211.1 Designator212.1 LD33.3 V1.2@-72.022,-11.303

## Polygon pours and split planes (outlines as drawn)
GND on Top Layer "Top Layer-GND" (hatched 45Degree grid 0.889 track 0.127, remove dead copper, pour order 4): -86.538,-0.025 -86.538,-96.672 -0.178,-96.672 -0.178,0 0.025,0
NetC4_2 on Top Layer "Top Layer-NetC4_2" (hatched 45Degree grid 0.889 track 0.127, remove dead copper, pour order 2): -86.5,-98.97 -86.5,-140.97 -0.394,-140.97 -0.394,-98.97
GND on Bottom Layer "Bottom Layer-GND" (hatched 45Degree grid 0.889 track 0.127, remove dead copper, pour order 6): -86.741,-0.051 -86.741,-96.698 -0.381,-96.698 -0.381,-0.025 -0.178,-0.025

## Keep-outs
Keep-Out Layer:
  the board outline again, w0.025

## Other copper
Top Layer:
  pour cut-out: -27.118,-47.426 ccw(c-27.039,-69.779) -49.379,-69.001 ccw(c-27.783,-69.029) -26.478,-90.586 ccw(c-27.076,-68.672) -5.158,-69.044 ccw(c-26.559,-68.821)
  pour cut-out: -82.601,-43.485 -82.601,-93.98 -71.831,-93.98 -71.831,-43.434
Bottom Layer:
  pour cut-out: -26.965,-47.578 ccw(c-26.886,-69.932) -49.226,-69.154 ccw(c-27.631,-69.182) -26.325,-90.738 ccw(c-26.924,-68.824) -5.006,-69.196 ccw(c-26.407,-68.973)
  pour cut-out: -82.601,-43.485 -82.601,-93.98 -71.831,-93.98 -71.831,-43.434

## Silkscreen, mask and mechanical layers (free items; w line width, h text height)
Top Overlay:
  drawing of 459 lines, arcs and shapes, not listed
  text "3.3V" at -60.516,-6.528 h0.8
  text "+" at -85.623,-20.345 h1
  text "-" at -85.573,-32.106 h1
  text "-" at -16.078,-41.834 h1
  text "+" at -22.86,-41.935 h1
  text "PY32T090 TouchDemo V1.1" at -68.441,-42.24 h1
  text "VCC" at -7.303,-42.905 h1
  text "WWW.PUYASEMI.COM" at -66.485,-44.272 h1
  text "SWDIO" at -7.956,-45.477 h1
  text "GND" at -7.28,-48.049 h1
  text "2025.06.05" at -63.576,-49.454 h1
  text "SWCLK" at -8.196,-50.62 h1
  text "RST" at -7.227,-53.192 h1
  text "VCC" at -5.63,-85.801 h0.8
  text "RXD_PD5" at -8.357,-88.646 h0.8
  text "TXD_PD6" at -8.235,-91.084 h0.8
  text "GND" at -5.591,-93.497 h0.8

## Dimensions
-86.5,-140.97 to -86.5,0 on Top Overlay
-86.5,-140.97 to -0.394,-140.97 on Top Overlay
